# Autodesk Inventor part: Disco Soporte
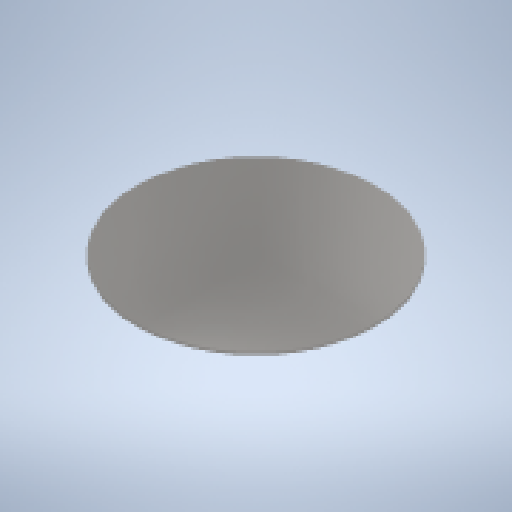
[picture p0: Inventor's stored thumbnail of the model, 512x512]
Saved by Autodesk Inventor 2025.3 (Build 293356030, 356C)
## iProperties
Created: 2025-10
Part Number: Disco Soporte
Material: Hierro, fundido
Document SubType Name: Modeling
Designer: Asus
Density: 7.15 g/cm^3
Appearance: Semipulido
Author: Asus
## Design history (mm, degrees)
sketch "Boceto1"
  geometry: C1 r 90 at (0, 0); 1 further point
  constraints: 1 centre point, 1 coincident
  dimensions: "d0" = 180 diameter of C1
extrude "Extrusión1" new body sketch "Boceto1" distance "d1" = 2; taper "d2" = 0 deg
node "Sólido1"
